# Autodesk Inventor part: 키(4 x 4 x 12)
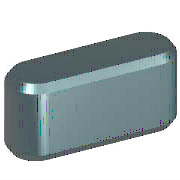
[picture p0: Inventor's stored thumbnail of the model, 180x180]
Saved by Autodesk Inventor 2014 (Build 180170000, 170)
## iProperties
IsCustomPart: 0
Created: 2009-02
Part Number: 키(4 x 4 x 12)
Material: 강철, 연강
Description: 키 및 해당 키홈
Document SubType Name: Modeling
Standard: KS B 1311
Designer: KYOUNG IL JANG
Standards Organization: KS
Language: ko-KR
Size Designation: 4 x 4 x 12
Categories: <MemberInstance><Categories><Category DisplayName="샤프트 부품" InternalName="7f7aeb1f-a693-4053-b835-cee3144e0d98" Mnemonic="SHFT"><Category DisplayName="키" Interna
Density: 7.86 g/cm^3
Mass: 1.38739 g
Surface Area: 1.94869 cm^2
Volume: 0.176513 cm^3
Appearance: Steel
Author: KYOUNG IL JANG
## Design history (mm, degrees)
sketch "스케치1"
  geometry: L1 (2, 2)-(10, 2); L2 (10, -2)-(2, -2); L3 (0, 9.4)-(0, -7.4) reference; L4 (-5, 0)-(30, 0) reference; L5 (12, 0)-(12, 7); A1 r 2 centre (2, 0) between (2, 2) and (2, -2); A2 r 2 centre (10, 0) between (10, -2) and (10, 2)
  constraints: 6 end point, 5 point on circle, 4 tangent, 3 point on line, 2 centre point, 1 horizontal, 1 parallel, 1 perpendicular
  dimensions: "d0" = 2 radius of A1 (= 0.5 x PB); "d13" = 2 radius of A2 (= 0.5 x PB); "d14" = 12 distance between parallel lines of L5 L3 (= NLG)
extrude "본체1" new body sketch "스케치1" taper "d3" = 0 deg; stored distance "d4" = 10
workplane "Work Plane3"
body "Solid1"
workplane "Work Plane1"
workplane "Work Plane2"
chamfer "모따기1" distance "d8" = 0.25 (= PHH); stored, may be unused: second distance "d9" = 0.25 (= PHH), angle "d15" = 45 deg
other parameters: "d1" = -2.5 (= -PNT), "d2" = 1.5 (= PH - PNT), "NLG" = 12 [user parameter; used in 3 equation terms], "PB" = 4 [user parameter; used in 2 equation terms], "PNT" = 2.5 [user parameter; used in 2 equation terms], "PH" = 4 [user parameter; used in 1 equation term], "PHH" = 0.25 [user parameter; used in 2 equation terms], "d10" = 0, "d16" = 0, "d17" = 0, "d18" = 0, "PLB2" = 12 (= NLG) [user parameter], "WDMAX" = 12 [user parameter], "PLB1" = 12 (= NLG) [user parameter], "RR" = 0.08 [user parameter], "PUEB" = 1.8 [user parameter]
